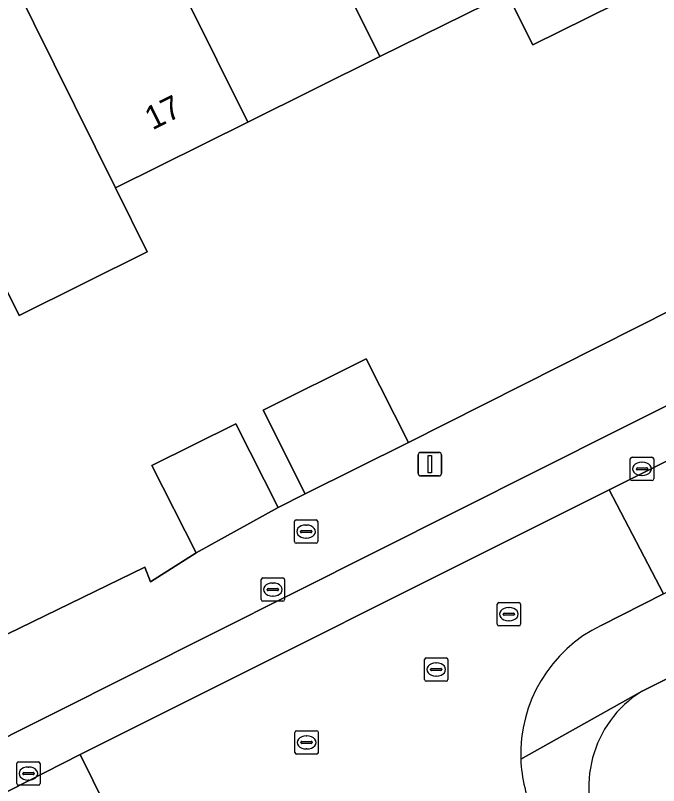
# Model space of a CAD drawing. Extents: x 157793 to 159380, y 380877 to 382313.
# Drawn here: x 158297.85 to 158325.35, y 381486.85 to 381519.79 of the extents above; entities that cross this region are included whole.
import ezdxf

# ---------------------------------------------------------------- set-up
doc = ezdxf.new("R2010")
doc.units = 0
for name, color, linetype in [('IMGEO_Brandkraan', 7, 'Continuous'), ('IMGEO_Erf', 7, 'Continuous'), ('IMGEO_Groenvoorziening', 7, 'Continuous'), ('IMGEO_Kolk', 7, 'Continuous'), ('IMGEO_Lichtmast', 7, 'Continuous'), ('IMGEO_Pand', 7, 'Continuous'), ('IMGEO_Pand_nummerreeks', 7, 'Continuous'), ('IMGEO_Parkeervlak_open', 7, 'Continuous'), ('IMGEO_Rijbaan_lokaal_open', 7, 'Continuous'), ('IMGEO_Rioolput', 7, 'Continuous'), ('IMGEO_Voetpad_open', 7, 'Continuous')]:
    doc.layers.add(name, color=color, linetype=linetype)

msp = doc.modelspace()

# ---------------------------------------------------------------- linework, layer by layer
at = {"layer": 'IMGEO_Brandkraan'}
for p, q in [((158309.781, 381497.289), (158309.781, 381498.141)), ((158309.856, 381498.215), (158310.708, 381498.215)), ((158310.782, 381498.141), (158310.782, 381497.289)), ((158310.04, 381497.709), (158310.04, 381497.721)), ((158310.083, 381497.758), (158310.481, 381497.758)), ((158310.269, 381497.995), (158310.294, 381497.995)), ((158310.524, 381497.721), (158310.524, 381497.709)), ((158310.478, 381497.672), (158310.08, 381497.672)), ((158310.292, 381497.435), (158310.267, 381497.435)), ((158310.708, 381497.215), (158309.856, 381497.215))]:
    msp.add_line(p, q, dxfattribs=at)
for points in [[(158309.781, 381497.289), (158309.781, 381498.141)], [(158309.856, 381498.215), (158310.708, 381498.215)], [(158310.782, 381498.141), (158310.782, 381497.289)], [(158310.708, 381497.215), (158309.856, 381497.215)]]:
    msp.add_lwpolyline(points, dxfattribs=at)
for centre, radius, start, end in [((158309.858, 381498.139), 0.0765, 91.552, 178.448), ((158309.858, 381498.139), 0.0765, 91.552, 178.448), ((158310.706, 381498.139), 0.0765, 1.552, 88.448), ((158310.706, 381498.139), 0.0765, 1.552, 88.448), ((158310.08, 381497.718), 0.0403, 85.8775, 175.7526), ((158310.485, 381497.72), 0.0386, 1.7309, 96.639), ((158310.077, 381497.708), 0.0366, 178.938, 274.7102), ((158310.481, 381497.715), 0.043, 264.8664, 352.4533), ((158309.858, 381497.291), 0.0765, 181.552, 268.448), ((158309.858, 381497.291), 0.0765, 181.552, 268.448), ((158310.706, 381497.291), 0.0765, 271.552, 358.448), ((158310.706, 381497.291), 0.0765, 271.552, 358.448)]:
    msp.add_arc(centre, radius, start, end, dxfattribs=at)
for centre, major_axis, ratio, start_param, end_param in [((158310.268, 381497.715), (-0.387, 0.002), 0.722429, 4.712389, 7.853982), ((158310.293, 381497.715), (-0.39, 0.002), 0.717154, 1.570796, 4.712389)]:
    msp.add_ellipse(centre, major_axis=major_axis, ratio=ratio, start_param=start_param, end_param=end_param, dxfattribs=at)
at = {"layer": 'IMGEO_Erf'}
for points in [[(158325.833, 381521.444), (158319.975, 381518.534), (158318.883, 381520.732), (158313.439, 381518.028), (158307.787, 381515.221), (158302.135, 381512.413), (158303.492, 381509.678), (158298.009, 381506.957), (158297.165, 381508.658)], [(158295.901, 381492.555), (158303.384, 381496.2), (158303.625, 381495.571), (158305.588, 381496.813), (158303.686, 381500.536), (158307.272, 381502.319), (158309.088, 381498.746), (158310.247, 381499.326), (158308.441, 381502.906), (158312.854, 381505.11), (158314.661, 381501.53), (158325.988, 381507.244), (158331.554, 381510.024), (158334.071, 381511.302), (158354.167, 381521.141)]]:
    msp.add_lwpolyline(points, dxfattribs=at)
at = {"layer": 'IMGEO_Groenvoorziening'}
msp.add_lwpolyline([(158348.584, 381494.228), (158345.094, 381501.119), (158324.627, 381490.884)], dxfattribs=at)
msp.add_arc((158327.199, 381486.794), 4.832, 122.1631, 208.0032, dxfattribs=at)
at = {"layer": 'IMGEO_Kolk'}
for p, q in [((158324.143, 381499.973), (158324.143, 381500.825)), ((158324.218, 381500.899), (158325.07, 381500.899)), ((158325.144, 381500.825), (158325.144, 381499.973)), ((158324.402, 381500.393), (158324.402, 381500.405)), ((158324.84, 381500.356), (158324.442, 381500.356)), ((158324.445, 381500.442), (158324.843, 381500.442)), ((158324.631, 381500.679), (158324.656, 381500.679)), ((158324.886, 381500.405), (158324.886, 381500.393)), ((158324.654, 381500.119), (158324.629, 381500.119)), ((158325.07, 381499.899), (158324.218, 381499.899)), ((158297.984, 381487.868), (158298.836, 381487.868)), ((158297.909, 381486.942), (158297.909, 381487.794)), ((158298.397, 381487.648), (158298.422, 381487.648)), ((158298.91, 381487.794), (158298.91, 381486.942)), ((158298.168, 381487.362), (158298.168, 381487.374)), ((158298.606, 381487.325), (158298.208, 381487.325)), ((158298.211, 381487.411), (158298.609, 381487.411)), ((158298.652, 381487.374), (158298.652, 381487.362)), ((158298.836, 381486.868), (158297.984, 381486.868)), ((158298.42, 381487.088), (158298.395, 381487.088))]:
    msp.add_line(p, q, dxfattribs=at)
for points in [[(158324.143, 381499.973), (158324.143, 381500.825)], [(158324.218, 381500.899), (158325.07, 381500.899)], [(158325.144, 381500.825), (158325.144, 381499.973)], [(158325.07, 381499.899), (158324.218, 381499.899)], [(158297.984, 381487.868), (158298.836, 381487.868)], [(158297.909, 381486.942), (158297.909, 381487.794)], [(158298.91, 381487.794), (158298.91, 381486.942)], [(158298.836, 381486.868), (158297.984, 381486.868)]]:
    msp.add_lwpolyline(points, dxfattribs=at)
for centre, radius, start, end in [((158324.22, 381500.823), 0.0765, 91.552, 178.448), ((158324.22, 381500.823), 0.0765, 91.552, 178.448), ((158325.068, 381500.823), 0.0765, 1.552, 88.448), ((158325.068, 381500.823), 0.0765, 1.552, 88.448), ((158324.442, 381500.402), 0.0403, 85.8775, 175.7526), ((158324.439, 381500.392), 0.0366, 178.938, 274.7102), ((158324.843, 381500.399), 0.043, 264.8664, 352.4533), ((158324.847, 381500.404), 0.0386, 1.7309, 96.639), ((158324.22, 381499.975), 0.0765, 181.552, 268.448), ((158324.22, 381499.975), 0.0765, 181.552, 268.448), ((158325.068, 381499.975), 0.0765, 271.552, 358.448), ((158325.068, 381499.975), 0.0765, 271.552, 358.448), ((158297.986, 381487.792), 0.0765, 91.552, 178.448), ((158297.986, 381487.792), 0.0765, 91.552, 178.448), ((158298.834, 381487.792), 0.0765, 1.552, 88.448), ((158298.834, 381487.792), 0.0765, 1.552, 88.448), ((158298.208, 381487.371), 0.0403, 85.8775, 175.7526), ((158298.205, 381487.361), 0.0366, 178.938, 274.7102), ((158298.609, 381487.368), 0.043, 264.8664, 352.4533), ((158298.613, 381487.373), 0.0386, 1.7309, 96.639), ((158297.986, 381486.944), 0.0765, 181.552, 268.448), ((158297.986, 381486.944), 0.0765, 181.552, 268.448), ((158298.834, 381486.944), 0.0765, 271.552, 358.448), ((158298.834, 381486.944), 0.0765, 271.552, 358.448)]:
    msp.add_arc(centre, radius, start, end, dxfattribs=at)
for centre, major_axis, ratio, start_param, end_param in [((158324.63, 381500.399), (-0.387, 0.002), 0.722429, 4.712389, 7.853982), ((158324.655, 381500.399), (-0.39, 0.002), 0.717154, 1.570796, 4.712389), ((158298.396, 381487.368), (-0.387, 0.002), 0.722429, 4.712389, 7.853982), ((158298.421, 381487.368), (-0.39, 0.002), 0.717154, 1.570796, 4.712389)]:
    msp.add_ellipse(centre, major_axis=major_axis, ratio=ratio, start_param=start_param, end_param=end_param, dxfattribs=at)
at = {"layer": 'IMGEO_Lichtmast'}
for p, q in [((158315.177, 381501.1), (158315.967, 381501.1)), ((158315.967, 381501.1), (158315.177, 381501.1)), ((158315.077, 381500.2), (158315.077, 381501)), ((158315.077, 381501), (158315.077, 381500.2)), ((158316.067, 381501), (158316.067, 381500.2)), ((158316.067, 381500.2), (158316.067, 381501)), ((158315.967, 381500.1), (158315.177, 381500.1)), ((158315.177, 381500.1), (158315.967, 381500.1))]:
    msp.add_line(p, q, dxfattribs=at)
msp.add_lwpolyline([(158315.497, 381500.975), (158315.647, 381500.975), (158315.647, 381500.225), (158315.497, 381500.225), (158315.497, 381500.975)], dxfattribs=at)
for centre, start, end in [((158315.177, 381501), 90, 180), ((158315.177, 381501), 90, 180), ((158315.967, 381501), 0, 90), ((158315.967, 381501), 360, 90), ((158315.177, 381500.2), 180, 270), ((158315.177, 381500.2), 180, 270), ((158315.967, 381500.2), 270, 0), ((158315.967, 381500.2), 270, 0)]:
    msp.add_arc(centre, 0.1, start, end, dxfattribs=at)
at = {"layer": 'IMGEO_Pand'}
for points in [[(158303.832, 381523.2), (158302.195, 381526.496), (158299.372, 381525.094), (158298.003, 381527.786), (158294.856, 381530.887), (158294.347, 381531.783), (158292.885, 381531.04), (158293.377, 381530.049), (158302.135, 381512.413), (158307.787, 381515.221)], [(158293.377, 381530.049), (158292.885, 381531.04), (158289.254, 381529.194), (158293.752, 381520.252), (158293.672, 381518.153), (158292.362, 381517.502), (158292.878, 381516.462), (158293.039, 381516.543), (158296.484, 381509.606), (158296.653, 381509.69), (158297.165, 381508.658), (158298.009, 381506.957), (158303.492, 381509.678), (158302.135, 381512.413)], [(158316.19, 381526.556), (158318.883, 381520.732), (158319.975, 381518.534), (158325.833, 381521.444), (158321.835, 381529.36)], [(158316.19, 381526.556), (158315.082, 381528.788), (158309.478, 381526.004), (158313.439, 381518.028), (158318.883, 381520.732)], [(158303.832, 381523.2), (158307.787, 381515.221), (158313.439, 381518.028), (158309.478, 381526.004)], [(158310.247, 381499.326), (158314.661, 381501.53), (158312.854, 381505.11), (158308.441, 381502.906)], [(158305.588, 381496.813), (158309.088, 381498.746), (158307.272, 381502.319), (158303.686, 381500.536)]]:
    msp.add_lwpolyline(points, close=True, dxfattribs=at)
at = {"layer": 'IMGEO_Parkeervlak_open'}
for points in [[(158360.378, 381520.424), (158339.842, 381510.182), (158335.434, 381507.954), (158328.215, 381504.357), (158323.691, 381502.101), (158292.396, 381486.391), (158290.721, 381485.284)], [(158295.372, 381485.52), (158300.625, 381488.183), (158323.239, 381499.498), (158364.219, 381519.993)]]:
    msp.add_lwpolyline(points, dxfattribs=at)
at = {"layer": 'IMGEO_Rijbaan_lokaal_open'}
msp.add_lwpolyline([(158429.532, 381546.784), (158430.537, 381547.261), (158428.291, 381551.786), (158422.95, 381549.11), (158406.043, 381540.758), (158405.49, 381540.487), (158405.162, 381540.325), (158390.456, 381533.119), (158390.104, 381532.932), (158364.219, 381519.993), (158323.239, 381499.498), (158325.561, 381495.049), (158366.656, 381515.626), (158376.866, 381520.672)], close=True, dxfattribs=at)
for points in [[(158322.894, 381493.705), (158325.561, 381495.049), (158323.239, 381499.498), (158300.625, 381488.183), (158302.784, 381483.793), (158307.7, 381486.207)], [(158290.513, 381482.525), (158289.203, 381481.576), (158288.861, 381481.321), (158287.186, 381480.143), (158236.126, 381444.916), (158238.977, 381440.815), (158290.279, 381476.177), (158294.12, 381478.763), (158298.335, 381481.315), (158302.02, 381483.392), (158302.784, 381483.793), (158300.625, 381488.183), (158295.372, 381485.52)]]:
    msp.add_lwpolyline(points, dxfattribs=at)
for centre, radius, start, end in [((158325.58, 381488.204), 6.122, 116.0239, 182.0397), ((158325.589, 381488.204), 6.131, 182.0417, 205.0773)]:
    msp.add_arc(centre, radius, start, end, dxfattribs=at)
at = {"layer": 'IMGEO_Rioolput'}
for p, q in [((158308.36, 381494.811), (158308.36, 381495.663)), ((158308.435, 381495.737), (158309.287, 381495.737)), ((158308.848, 381495.517), (158308.873, 381495.517)), ((158309.361, 381495.663), (158309.361, 381494.811)), ((158308.619, 381495.231), (158308.619, 381495.243)), ((158309.057, 381495.194), (158308.659, 381495.194)), ((158308.662, 381495.28), (158309.06, 381495.28)), ((158309.103, 381495.243), (158309.103, 381495.231)), ((158308.871, 381494.957), (158308.846, 381494.957)), ((158309.287, 381494.737), (158308.435, 381494.737)), ((158318.45, 381493.758), (158318.45, 381494.61)), ((158318.525, 381494.684), (158319.377, 381494.684)), ((158318.938, 381494.464), (158318.963, 381494.464)), ((158319.451, 381494.61), (158319.451, 381493.758)), ((158318.709, 381494.178), (158318.709, 381494.19)), ((158319.147, 381494.141), (158318.749, 381494.141)), ((158318.752, 381494.227), (158319.15, 381494.227)), ((158319.193, 381494.19), (158319.193, 381494.178)), ((158318.961, 381493.904), (158318.936, 381493.904)), ((158319.377, 381493.684), (158318.525, 381493.684)), ((158315.345, 381491.392), (158315.345, 381492.244)), ((158315.42, 381492.318), (158316.272, 381492.318)), ((158316.346, 381492.244), (158316.346, 381491.392)), ((158315.604, 381491.812), (158315.604, 381491.824)), ((158315.647, 381491.861), (158316.045, 381491.861)), ((158315.833, 381492.098), (158315.858, 381492.098)), ((158316.088, 381491.824), (158316.088, 381491.812)), ((158316.042, 381491.775), (158315.644, 381491.775)), ((158315.856, 381491.538), (158315.831, 381491.538)), ((158316.272, 381491.318), (158315.42, 381491.318)), ((158309.878, 381489.2), (158310.73, 381489.2)), ((158309.803, 381488.274), (158309.803, 381489.126)), ((158310.291, 381488.98), (158310.316, 381488.98)), ((158310.804, 381489.126), (158310.804, 381488.274)), ((158310.062, 381488.694), (158310.062, 381488.706)), ((158310.5, 381488.657), (158310.102, 381488.657)), ((158310.105, 381488.743), (158310.503, 381488.743)), ((158310.546, 381488.706), (158310.546, 381488.694)), ((158310.73, 381488.2), (158309.878, 381488.2)), ((158310.314, 381488.42), (158310.289, 381488.42))]:
    msp.add_line(p, q, dxfattribs=at)
for points in [[(158308.36, 381494.811), (158308.36, 381495.663)], [(158308.435, 381495.737), (158309.287, 381495.737)], [(158309.361, 381495.663), (158309.361, 381494.811)], [(158309.287, 381494.737), (158308.435, 381494.737)], [(158318.45, 381493.758), (158318.45, 381494.61)], [(158318.525, 381494.684), (158319.377, 381494.684)], [(158319.451, 381494.61), (158319.451, 381493.758)], [(158319.377, 381493.684), (158318.525, 381493.684)], [(158315.345, 381491.392), (158315.345, 381492.244)], [(158315.42, 381492.318), (158316.272, 381492.318)], [(158316.346, 381492.244), (158316.346, 381491.392)], [(158316.272, 381491.318), (158315.42, 381491.318)], [(158309.878, 381489.2), (158310.73, 381489.2)], [(158309.803, 381488.274), (158309.803, 381489.126)], [(158310.804, 381489.126), (158310.804, 381488.274)], [(158310.73, 381488.2), (158309.878, 381488.2)]]:
    msp.add_lwpolyline(points, dxfattribs=at)
for centre, radius, start, end in [((158308.437, 381495.661), 0.0765, 91.552, 178.448), ((158308.437, 381495.661), 0.0765, 91.552, 178.448), ((158309.285, 381495.661), 0.0765, 1.552, 88.448), ((158309.285, 381495.661), 0.0765, 1.552, 88.448), ((158308.659, 381495.24), 0.0403, 85.8775, 175.7526), ((158308.656, 381495.23), 0.0366, 178.938, 274.7102), ((158309.06, 381495.237), 0.043, 264.8664, 352.4533), ((158309.064, 381495.242), 0.0386, 1.7309, 96.639), ((158308.437, 381494.813), 0.0765, 181.552, 268.448), ((158308.437, 381494.813), 0.0765, 181.552, 268.448), ((158309.285, 381494.813), 0.0765, 271.552, 358.448), ((158309.285, 381494.813), 0.0765, 271.552, 358.448), ((158318.527, 381494.608), 0.0765, 91.552, 178.448), ((158318.527, 381494.608), 0.0765, 91.552, 178.448), ((158319.375, 381494.608), 0.0765, 1.552, 88.448), ((158319.375, 381494.608), 0.0765, 1.552, 88.448), ((158318.749, 381494.187), 0.0403, 85.8775, 175.7526), ((158318.746, 381494.177), 0.0366, 178.938, 274.7102), ((158319.15, 381494.184), 0.043, 264.8664, 352.4533), ((158319.154, 381494.189), 0.0386, 1.7309, 96.639), ((158318.527, 381493.76), 0.0765, 181.552, 268.448), ((158318.527, 381493.76), 0.0765, 181.552, 268.448), ((158319.375, 381493.76), 0.0765, 271.552, 358.448), ((158319.375, 381493.76), 0.0765, 271.552, 358.448), ((158315.422, 381492.242), 0.0765, 91.552, 178.448), ((158315.422, 381492.242), 0.0765, 91.552, 178.448), ((158316.27, 381492.242), 0.0765, 1.552, 88.448), ((158316.27, 381492.242), 0.0765, 1.552, 88.448), ((158315.644, 381491.821), 0.0403, 85.8775, 175.7526), ((158315.641, 381491.811), 0.0366, 178.938, 274.7102), ((158316.045, 381491.818), 0.043, 264.8664, 352.4533), ((158316.049, 381491.823), 0.0386, 1.7309, 96.639), ((158315.422, 381491.394), 0.0765, 181.552, 268.448), ((158315.422, 381491.394), 0.0765, 181.552, 268.448), ((158316.27, 381491.394), 0.0765, 271.552, 358.448), ((158316.27, 381491.394), 0.0765, 271.552, 358.448), ((158309.88, 381489.124), 0.0765, 91.552, 178.448), ((158309.88, 381489.124), 0.0765, 91.552, 178.448), ((158310.728, 381489.124), 0.0765, 1.552, 88.448), ((158310.728, 381489.124), 0.0765, 1.552, 88.448), ((158310.102, 381488.703), 0.0403, 85.8775, 175.7526), ((158310.099, 381488.693), 0.0366, 178.938, 274.7102), ((158310.503, 381488.7), 0.043, 264.8664, 352.4533), ((158310.507, 381488.705), 0.0386, 1.7309, 96.639), ((158309.88, 381488.276), 0.0765, 181.552, 268.448), ((158309.88, 381488.276), 0.0765, 181.552, 268.448), ((158310.728, 381488.276), 0.0765, 271.552, 358.448), ((158310.728, 381488.276), 0.0765, 271.552, 358.448)]:
    msp.add_arc(centre, radius, start, end, dxfattribs=at)
for centre, major_axis, ratio, start_param, end_param in [((158308.847, 381495.237), (-0.387, 0.002), 0.722429, 4.712389, 7.853982), ((158308.872, 381495.237), (-0.39, 0.002), 0.717154, 1.570796, 4.712389), ((158318.937, 381494.184), (-0.387, 0.002), 0.722429, 4.712389, 7.853982), ((158318.962, 381494.184), (-0.39, 0.002), 0.717154, 1.570796, 4.712389), ((158315.832, 381491.818), (-0.387, 0.002), 0.722429, 4.712389, 7.853982), ((158315.857, 381491.818), (-0.39, 0.002), 0.717154, 1.570796, 4.712389), ((158310.29, 381488.7), (-0.387, 0.002), 0.722429, 4.712389, 7.853982), ((158310.315, 381488.7), (-0.39, 0.002), 0.717154, 1.570796, 4.712389)]:
    msp.add_ellipse(centre, major_axis=major_axis, ratio=ratio, start_param=start_param, end_param=end_param, dxfattribs=at)
at = {"layer": 'IMGEO_Voetpad_open'}
for points in [[(158393.565, 381539.204), (158390.943, 381537.901), (158388.228, 381536.549), (158387.942, 381536.406), (158367.05, 381525.999), (158364.97, 381526.517), (158361.964, 381525.035), (158361.66, 381524.885), (158359.996, 381524.036), (158359.971, 381524.023), (158354.167, 381521.141), (158334.071, 381511.302), (158331.554, 381510.024), (158325.988, 381507.244), (158314.661, 381501.53), (158310.247, 381499.326), (158309.088, 381498.746), (158305.588, 381496.813), (158303.625, 381495.571), (158303.384, 381496.2), (158295.901, 381492.555)], [(158319.462, 381487.986), (158324.627, 381490.884), (158345.094, 381501.119), (158348.584, 381494.228), (158349.93, 381494.878), (158346.435, 381501.779), (158371.522, 381514.342), (158375.088, 381507.338), (158376.436, 381508.005), (158372.857, 381515.012), (158398.164, 381527.551)], [(158290.721, 381485.284), (158292.396, 381486.391), (158323.691, 381502.101), (158328.215, 381504.357), (158335.434, 381507.954), (158339.842, 381510.182), (158360.378, 381520.424)], [(158325.561, 381495.049), (158322.894, 381493.705)], [(158324.627, 381490.884), (158319.462, 381487.986)]]:
    msp.add_lwpolyline(points, dxfattribs=at)
for centre, radius, start, end in [((158325.58, 381488.204), 6.122, 116.0239, 182.0397), ((158327.199, 381486.794), 4.832, 122.1631, 208.0032), ((158325.589, 381488.204), 6.131, 182.0417, 205.0773)]:
    msp.add_arc(centre, radius, start, end, dxfattribs=at)

# ---------------------------------------------------------------- texts
at = {"layer": 'IMGEO_Pand_nummerreeks'}
msp.add_text('17', height=1, rotation=26.4191, dxfattribs=at).set_placement((158303.709, 381514.869))

doc.saveas('drawing.dxf')
